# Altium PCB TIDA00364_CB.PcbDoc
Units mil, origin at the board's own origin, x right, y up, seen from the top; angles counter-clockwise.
Board outline 10290 x 3320 mil, 2 copper layers (Top Layer, Bottom Layer), stack 62 mil thick; 70 components, 9 nets, 112 pads, 0 vias.
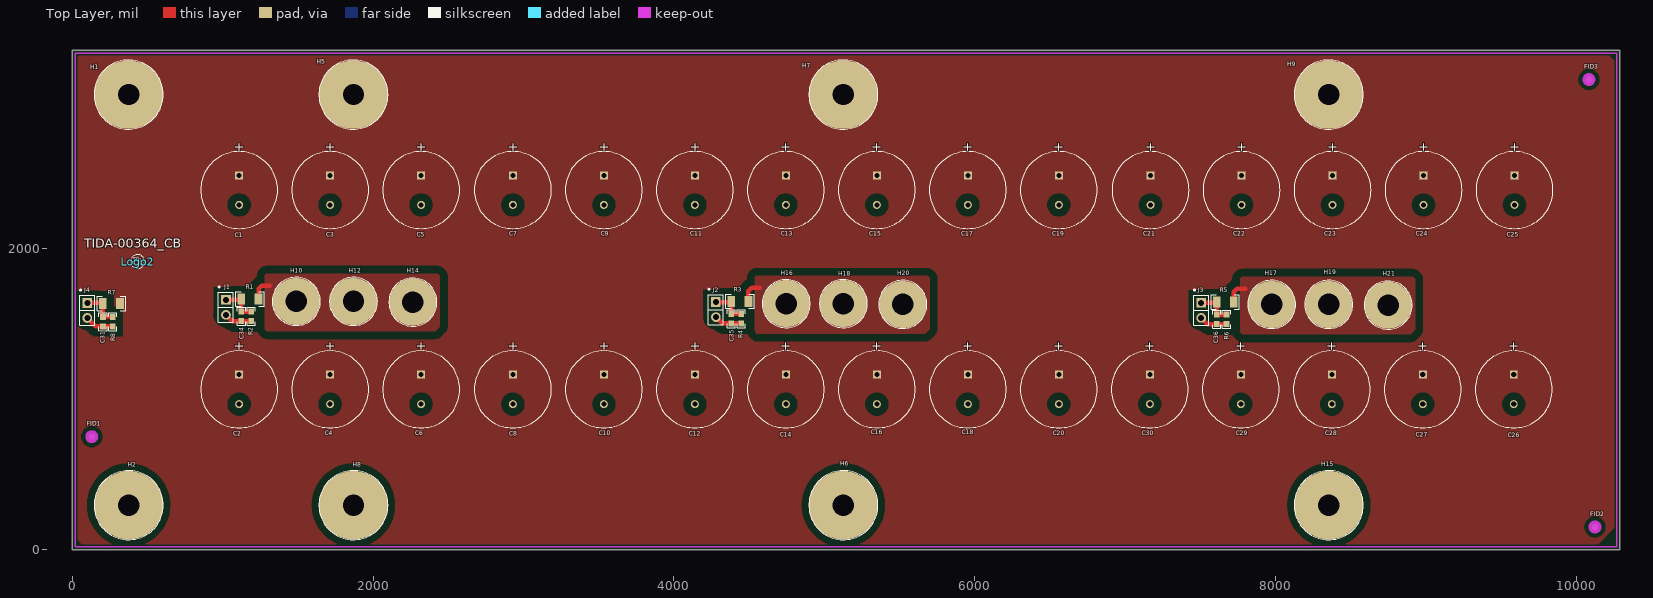
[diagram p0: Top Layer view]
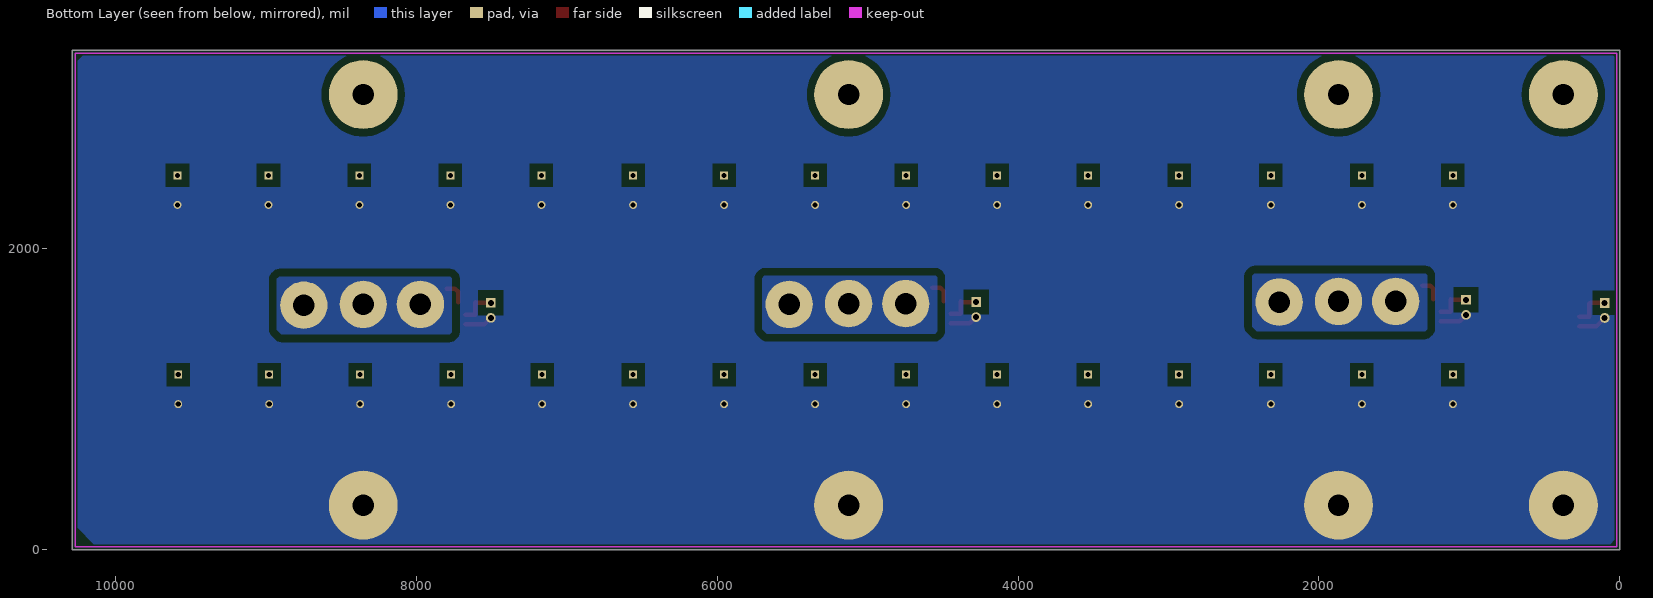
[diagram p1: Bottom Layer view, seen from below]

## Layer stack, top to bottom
Top Solder: solder mask 0.4, Solder Resist, Dk 3.5
Top Layer: signal copper 1.4
Dielectric1: core 59.2, FR-4, Dk 4.8
Bottom Layer: signal copper 1.4
Bottom Solder: solder mask 0.4, Solder Resist, Dk 3.5

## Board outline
0,0 0,3320 10290,3320 10290,0

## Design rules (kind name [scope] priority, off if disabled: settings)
AcuteAngle [All] p1: minimum=4.50000000000000E+0001 checktracksonly=FALSE
AssemblyTestPointUsage [All] p1: valid=2
Clearance Clearance_Boardedge_poly [OnCopper and InPolygon vs IsKeepOut] p1: gap=10
Clearance Clearance_PLANE [InPoly] p2: gap=50
Clearance "Clearance_via_thr pin" [IsVia vs IsThruPin] p3: gap=8
Clearance "Clearance_pad _class" [InPadClass('u12,u4,u5')] p4: gap=7.8
Clearance "SMD to Via" [IsSMTPin vs IsVia] p5: gap=8
Clearance [All] p6: gap=8
DiffPairsRouting DiffPair_DiffPairsRouting [InDifferentialPair ('kan')] p1: maxlimit=10 minlimit=10 mostfreqgap=10 toplayer_minwidth=15 toplayer_maxwidth=15 toplayer_prefwidth=15 bottomlayer_minwidth=15 bottomlayer_maxwidth=15 bottomlayer_prefwidth=15 maxuncoupledlength=500
DiffPairsRouting DiffPair_DiffPairsRouting_1 [InDifferentialPair ('kan')] p2: maxlimit=10 minlimit=10 mostfreqgap=10 toplayer_minwidth=15 toplayer_maxwidth=15 toplayer_prefwidth=15 bottomlayer_minwidth=15 bottomlayer_maxwidth=15 bottomlayer_prefwidth=15 maxuncoupledlength=500
DiffPairsRouting [All] p3: maxlimit=100 minlimit=10 mostfreqgap=10 toplayer_minwidth=15 toplayer_maxwidth=15 toplayer_prefwidth=15 bottomlayer_minwidth=15 bottomlayer_maxwidth=15 bottomlayer_prefwidth=15 maxuncoupledlength=1000
FabricationTestPointUsage TestPointUsage [All] p1: valid=2 allowmultiple=FALSE
FabricationTestpoint Testpoint [All] p1: side=3 testpointundercomponent=TRUE minsize=40 maxsize=100 preferedsize=60 minholesize=0 maxholesize=40 preferedholesize=32 testpointgrid=1 allowsidetop=TRUE allowsidebottom=TRUE usegrid=TRUE gridtolerance=0.01
FanoutControl Fanout_LCC [IsLCC] p1: bgadir=Out bgaviamode=Centered fanoutstyle=Auto fanoutdirection=Alternating viagrid=1 // Fanout_LCC (Default Rule)
FanoutControl Fanout_BGA [IsBGA] p2: bgadir=Out bgaviamode=Centered fanoutstyle=Auto fanoutdirection=Alternating viagrid=1 // Fanout_BGA (Default Rule)
FanoutControl Fanout_Default [All] p4: bgadir=Out bgaviamode=Centered fanoutstyle=Auto fanoutdirection=Alternating viagrid=1 // Fanout_Default (Default Rule)
FanoutControl Fanout_Small [(CompPinCount < 5)] p5: bgadir=Out bgaviamode=Centered fanoutstyle=Auto fanoutdirection=OutThenIn viagrid=1 // Fanout_Small (Default Rule)
HoleSize [All] p1: absolutevalues=TRUE maxlimit=500 minlimit=7 maxpercent=80.000 minpercent=20.000
MatchedLengths DiffPair_MatchedLengths [InDifferentialPair ('kan')] p1: tolerance=1000 checknetsindiffpair=TRUE checkdiffpairvsdiffpair=FALSE checkxsignals=FALSE checkothers=FALSE
MatchedLengths DiffPair_MatchedLengths_1 [InDifferentialPair ('kan')] p2: tolerance=1000 checknetsindiffpair=TRUE checkdiffpairvsdiffpair=FALSE checkxsignals=FALSE checkothers=FALSE
MinimumAnnularRing [All] p1: minimumring=5
MinimumAnnularRing MinimumAnnularRing_ThermalPadVias [IsVia and InAnyComponent] p2: minimumring=5.91
MinimumSolderMaskSliver MinimumSolderMaskSliver_Logo [InComponentClass('Logo') vs InComponentClass('Logo')] p1: minsoldermaskwidth=0.7
MinimumSolderMaskSliver [All] p2: minsoldermaskwidth=3.94
PlaneClearance [All] p1: clearance=15
PlaneConnect [All] p1: planeconnectstyle=Direct reliefexpansion=10 reliefentries=4 reliefconductorwidth=10 reliefairgap=10
PolygonConnect [All] p1: connectstyle=Direct reliefconductorwidth=10 reliefentries=4 polygonreliefangle="90 Angle" airgapwidth=10
RoutingVias RoutingVias_power [InNetClass('POWER')] p1: holewidth=16 width=32 viastyle="Through Hole" minholewidth=7.87 minwidth=19.68 maxholewidth=16 maxwidth=32
RoutingVias ThermalPadVias [IsVia and InAnyComponent] p2: holewidth=8 width=20 viastyle="Through Hole" minholewidth=7.87 minwidth=19 maxholewidth=12 maxwidth=24
RoutingVias [All] p3: holewidth=16 width=32 viastyle="Through Hole" minholewidth=12 minwidth=24 maxholewidth=20 maxwidth=40
SMDToCorner [All] p1: distance=30000
SilkToSilkClearance [All] p1: silktosilkclearance=5
SilkToSolderMaskClearance SilkscreenOverComponentPads [IsPad] p1: minsilkscreentomaskgap=5 clearancetoexposedcopper=TRUE
SolderMaskExpansion [All] p1: expansion=3
Width Width_power [InNetClass('POWER')] p1: maxlimit=100 minlimit=8 preferedwidth=20
Width [All] p2: maxlimit=100 minlimit=10 preferedwidth=10 checkconnectedcopper=TRUE
16 further rules are at their usual default settings.

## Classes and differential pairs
component class FiducialMark: FID1 FID2 FID3
component class AssemblyNote: ZZ1 ZZ2 ZZ3
component class TIDA00364_CB_CapacitorBank: C1 C2 C3 C4 C5 C6 C7 C8 C9 C10 C11 C12 C13 C14 C15 C16 C17 C18 C19 C20 C21 C22 C23 C24 C25 C26 C27 C28 C29 C30 C31 C34 C35 C36 J1 J2 J3 J4 R1 R2 R3 R4 R5 R6 R7 R8
component class TIDA00364_CB_Hardware: FID1 FID2 FID3 H1 H2 H5 H6 H7 H8 H9 H10 H12 H14 H15 H16 H17 H18 H19 H20 H21 Logo2 ZZ1 ZZ2 ZZ3
component class Header: J1 J2 J3 J4

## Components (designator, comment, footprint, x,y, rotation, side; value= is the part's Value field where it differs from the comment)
C1 "UHE2A121MHD6" HE_1250x2000 1110,2390 r270 top
C2 "UHE2A121MHD6" HE_1250x2000 1110,1065 r270 top
C3 "UHE2A121MHD6" HE_1250x2000 1715,2390 r270 top
C4 "UHE2A121MHD6" HE_1250x2000 1715,1065 r270 top
C5 "UHE2A121MHD6" HE_1250x2000 2320,2390 r270 top
C6 "UHE2A121MHD6" HE_1250x2000 2320,1065 r270 top
C7 "UHE2A121MHD6" HE_1250x2000 2930,2390 r270 top
C8 "UHE2A121MHD6" HE_1250x2000 2930,1065 r270 top
C9 "UHE2A121MHD6" HE_1250x2000 3535,2390 r270 top
C10 "UHE2A121MHD6" HE_1250x2000 3535,1065 r270 top
C11 "UHE2A121MHD6" HE_1250x2000 4140,2390 r270 top
C12 "UHE2A121MHD6" HE_1250x2000 4140,1065 r270 top
C13 "UHE2A121MHD6" HE_1250x2000 4745,2390 r270 top
C14 "UHE2A121MHD6" HE_1250x2000 4745,1065 r270 top
C15 "UHE2A121MHD6" HE_1250x2000 5350,2390 r270 top
C16 "UHE2A121MHD6" HE_1250x2000 5350,1065 r270 top
C17 "UHE2A121MHD6" HE_1250x2000 5955,2390 r270 top
C18 "UHE2A121MHD6" HE_1250x2000 5955,1065 r270 top
C19 "UHE2A121MHD6" HE_1250x2000 6560,2390 r270 top
C20 "UHE2A121MHD6" HE_1250x2000 6560,1065 r270 top
C21 "UHE2A121MHD6" HE_1250x2000 7170,2390 r270 top
C22 "UHE2A121MHD6" HE_1250x2000 7775,2390 r270 top
C23 "UHE2A121MHD6" HE_1250x2000 8380,2390 r270 top
C24 "UHE2A121MHD6" HE_1250x2000 8985,2390 r270 top
C25 "UHE2A121MHD6" HE_1250x2000 9590,2390 r270 top
C26 "UHE2A121MHD6" HE_1250x2000 9585,1065 r270 top
C27 "UHE2A121MHD6" HE_1250x2000 8980,1065 r270 top
C28 "UHE2A121MHD6" HE_1250x2000 8375,1065 r270 top
C29 "UHE2A121MHD6" HE_1250x2000 7770,1065 r270 top
C30 "UHE2A121MHD6" HE_1250x2000 7165,1065 r270 top
C31 "C1608X7R1H103K" 0603 205,1515 r270 top
C34 "C1608X7R1H103K" 0603 1125,1550 r270 top
C35 "C1608X7R1H103K" 0603 4382.64,1535 r270 top
C36 "C1608X7R1H103K" 0603 7610,1530 r270 top
FID1 "Fiducial" Fiducial10-20 130,750 r90 top
FID2 "Fiducial" Fiducial10-20 10125,150 r90 top
FID3 "Fiducial" Fiducial10-20 10085,3125 r90 top
H1 "RM3X8MM 2701" "APM_RM3X8MM 2701"#1 375,3025.01 r0 top
H2 "RM3X8MM 2701" "APM_RM3X8MM 2701"#1 375,295.01 r0 top
H5 "RM3X8MM 2701" "APM_RM3X8MM 2701"#1 1870,3025.01 r0 top
H6 "RM3X8MM 2701" "APM_RM3X8MM 2701"#1 5127.64,295.01 r0 top
H7 "RM3X8MM 2701" "APM_RM3X8MM 2701"#1 5127.64,3025.01 r0 top
H8 "RM3X8MM 2701" "APM_RM3X8MM 2701"#1 1870,295.01 r0 top
H9 "RM3X8MM 2701" "APM_RM3X8MM 2701"#1 8355,3025.01 r0 top
H10 "RM3X8MM 2701" "APM_RM3X8MM 2701"#2 1490,1650.01 r0 top
H12 "RM3X8MM 2701" "APM_RM3X8MM 2701"#2 1870,1650.01 r0 top
H14 "RM3X8MM 2701" "APM_RM3X8MM 2701"#2 2265,1645.01 r0 top
H15 "RM3X8MM 2701" "APM_RM3X8MM 2701"#1 8355,295.01 r0 top
H16 "RM3X8MM 2701" "APM_RM3X8MM 2701"#2 4747.64,1635.01 r0 top
H17 "RM3X8MM 2701" "APM_RM3X8MM 2701"#2 7975,1630.01 r0 top
H18 "RM3X8MM 2701" "APM_RM3X8MM 2701"#2 5127.64,1635.01 r0 top
H19 "RM3X8MM 2701" "APM_RM3X8MM 2701"#2 8355,1630.01 r0 top
H20 "RM3X8MM 2701" "APM_RM3X8MM 2701"#2 5522.64,1630.01 r0 top
H21 "RM3X8MM 2701" "APM_RM3X8MM 2701"#2 8750,1625.01 r0 top
J1 "90120-0122" CONN_90120-0122 1021.93,1610.43 r270 top
J2 "90120-0122" CONN_90120-0122 4279.57,1595.43 r270 top
J3 "90120-0122" CONN_90120-0122 7506.93,1590.43 r270 top
J4 "90120-0122" CONN_90120-0122 100,1590 r270 top
Logo2 "Pb-Free Symbol" Pb-Free_Overlay_Small 435,1915 r0 top
R1 "CRCW1206200KFKEA" 1206 1181.93,1665.43 r180 top
R2 "CRCW060310K0FKEA" 0603 1190,1550 r90 top
R3 "CRCW1206200KFKEA" 1206 4439.57,1650.43 r180 top
R4 "CRCW060310K0FKEA" 0603 4447.64,1535 r90 top
R5 "CRCW1206200KFKEA" 1206 7666.93,1645.43 r180 top
R6 "CRCW060310K0FKEA" 0603 7675,1530 r90 top
R7 "CRCW1206200KFKEA" 1206 260,1635 r180 top
R8 "CRCW060310K0FKEA" 0603 270,1515 r90 top
ZZ1 "These assemblies are ESD sensitive, ESD precautions shall be observed." AssemblyNote 757.92,4115.63 r0 top
ZZ2 "These assemblies must be clean and free from flux and all contaminants. Use of no clean flux is not acceptable." AssemblyNote 757.92,4040.63 r0 top
ZZ3 "These assemblies must comply with workmanship standards IPC-A-610 Class 2, unless otherwise specified." AssemblyNote 755,3945 r0 top

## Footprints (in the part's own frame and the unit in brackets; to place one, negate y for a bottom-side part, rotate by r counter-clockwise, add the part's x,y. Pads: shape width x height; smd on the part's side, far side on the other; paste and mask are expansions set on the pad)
0603 [mm] "0603 from SM-752 data"
  rect 1x0.95 smd: 1(-0.8,0) 2(0.8,0)
  silkscreen extent -1.52,-0.69 1.52,0.69, body extent -0.87,-0.47 0.87,0.47, height 1
1206 [mm] "1206 from SM-752 data"
  rect 1.3x1.85 smd: 1(-1.45,0) 2(1.45,0)
  silkscreen extent -2.4,-1.21 2.4,1.21, body extent -1.7,-0.9 1.7,0.9, height 1.35
"APM_RM3X8MM 2701"#1 [mil] "Screw, Dia 6.7mm, Length 8mm, TH"
  round 458 hole 141.73: ""(0,0)
  silkscreen extent -230,-230 230,230, body extent -131,-132 132,132, height 94
"APM_RM3X8MM 2701"#2 [mil] "Screw, Dia 6.7mm, Length 8mm, TH"
  round 314.96 hole 141.73: ""(0,0)
  silkscreen extent -160,-160 160,160, body extent -131,-132 132,132, height 94
AssemblyNote [mil] "Assembly Note"
CONN_90120-0122 [mm] "Molex"
  rect 1.65x1.65 hole 1.016 mask+0: 1(-1.27,0)
  round 1.65 hole 1.016 mask+0: 2(1.27,0)
  silkscreen extent -3.56,-1.27 2.54,1.27, body extent -2.54,-1.27 2.54,1.27, height 9.29
Fiducial10-20 [mm]
  round 1 smd mask+0.5: 1(0,0)
  Top Layer keep-out circle w1.178: c0,0 r0.5
HE_1250x2000 [mm] "TH, 2-Leads, Dia 12.5, Pin Spacing 5mm"
  rect 1.35x1.35 hole 0.85: 1(-2.5,0)
  round 1.35 hole 0.85: 2(2.5,0)
  silkscreen extent -6.5,-6.5 6.5,6.5, body extent -6.45,-6.49 6.51,6.49, height 22
Pb-Free_Overlay_Small [mil]
  silkscreen extent -46,-46 46,46

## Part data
C1 C2 C3 C4 C5 C6 C7 C8 C9 C10 C11 C12 C13 C14 C15 C16 C17 C18 C19 C20 C21 C22 C23 C24 C25 C26 C27 C28 C29 C30: "CAP, AL, 120 µF, 100 V, +/- 20%, 0.16 ohm, TH"
C31 C34 C35 C36: "CAP, CERM, 0.01 µF, 50 V, +/- 10%, X7R, 0603"
FID1 FID2 FID3: "Fiducial mark.  There is nothing to buy or mount."
H1 H2 H5 H6 H7 H8 H9 H10 H12 H14 H15 H16 H17 H18 H19 H20 H21: "MACHINE SCREW PAN PHILLIPS M3"
J1 J2 J3 J4: "Header, 100mil, 2x1, Tin, TH"
Logo2: library part Pb-Free
R1 R3 R5 R7: "RES, 200 k, 1%, 0.25 W, 1206"
R2 R4 R6 R8: "RES, 10.0 k, 1%, 0.1 W, 0603"
ZZ1 ZZ2 ZZ3: library part AssemblyNote

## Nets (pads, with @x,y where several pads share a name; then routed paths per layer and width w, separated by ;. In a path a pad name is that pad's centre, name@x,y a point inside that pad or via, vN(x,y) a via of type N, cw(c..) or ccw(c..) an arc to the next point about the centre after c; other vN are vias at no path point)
48V: C1.1 C2.1 C3.1 C4.1 C5.1 C6.1 C7.1 C8.1 C9.1 C10.1 C11.1 C12.1 C13.1 C14.1 C15.1 C16.1 C17.1 C18.1 C19.1 C20.1 C21.1 C22.1 C23.1 C24.1 C25.1 C26.1 C27.1 C28.1 C29.1 C30.1 H1. H5. H7. H9. R7.1
48V_RTN: C1.2 C2.2 C3.2 C4.2 C5.2 C6.2 C7.2 C8.2 C9.2 C10.2 C11.2 C12.2 C13.2 C14.2 C15.2 C16.2 C17.2 C18.2 C19.2 C20.2 C21.2 C22.2 C23.2 C24.2 C25.2 C26.2 C27.2 C28.2 C29.2 C30.2 C31.2 C34.2 C35.2 C36.2 H2. H6. H8. H15. J1.2 J2.2 J3.2 J4.2 R2.1 R4.1 R6.1 R8.1 | length 749.7
  Top Layer w30: J4.2 156.5,1483.5 C31.2 R8.1 ; J1.2 1063.86,1518.5 C34.2 R2.1 ; J2.2 4321.5,1503.5 C35.2 R4.1 ; J3.2 7548.86,1498.5 C36.2 R6.1
PHASE_U: H10. H12. H14. R1.1 | length 153.3
  Top Layer w30: R1.1 1239.02,1734.02 1260,1755 1315,1755
PHASE_V: H16. H18. H20. R3.1 | length 153.3
  Top Layer w30: R3.1 4496.65,1719.02 4517.64,1740 4572.64,1740
PHASE_W: H17. H19. H21. R5.1 | length 153.3
  Top Layer w30: R5.1 7724.02,1714.02 7745,1735 7800,1735
PHV_U_FB: C34.1 J1.1 R1.2 R2.2 | length 254
  Top Layer w30: J1.1 1119.84,1660.43 R1.2 1124.84,1581.65 C34.1 R2.2
PHV_V_FB: C35.1 J2.1 R3.2 R4.2 | length 254
  Top Layer w30: J2.1 4377.48,1645.43 R3.2 4382.48,1566.65 C35.1 R4.2
PHV_W_FB: C36.1 J3.1 R5.2 R6.2 | length 254
  Top Layer w30: J3.1 7604.84,1640.43 R5.2 7609.84,1561.65 C36.1 R6.2
VDC_FB: C31.1 J4.1 R7.2 R8.2 | length 259.4
  Top Layer w30: J4.1 197.91,1640 R7.2 202.91,1548.58 C31.1 R8.2
pads on no net: FID1.1 FID2.1 FID3.1

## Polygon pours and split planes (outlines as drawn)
48V on Top Layer "Top Layer-No Net" (solid, remove dead copper, pour order 16): 60,3300 10205,3300 10270,3235 10270,160 10135,25 75,25 20,80 20,3260
PHASE_U on Top Layer "Top Layer-No Net" (solid, remove dead copper, pour order 9): 1305,1835 2430,1835 2445,1820 2445,1480 2415,1450 1295,1450 1280,1465 1280,1825 1290,1835
PHASE_V on Top Layer "Top Layer-No Net" (solid, remove dead copper, pour order 10): 4562.64,1820 5687.64,1820 5702.64,1805 5702.64,1465 5672.64,1435 4552.64,1435 4537.64,1450 4537.64,1810 4547.64,1820
PHASE_W on Top Layer "Top Layer-No Net" (solid, remove dead copper, pour order 11): 7790,1815 8915,1815 8930,1800 8930,1460 8900,1430 7780,1430 7765,1445 7765,1805 7775,1815
48V_RTN on Bottom Layer "Top Layer-No Net" (solid, remove dead copper, pour order 15): 60,3300 10205,3300 10270,3235 10270,160 10135,25 75,25 20,80 20,3260
PHASE_U on Bottom Layer "Top Layer-No Net" (solid, remove dead copper, pour order 14): 1305,1835 2430,1835 2445,1820 2445,1480 2415,1450 1295,1450 1280,1465 1280,1825 1290,1835
PHASE_V on Bottom Layer "Top Layer-No Net" (solid, remove dead copper, pour order 12): 4562.64,1820 5687.64,1820 5702.64,1805 5702.64,1465 5672.64,1435 4552.64,1435 4537.64,1450 4537.64,1810 4547.64,1820
PHASE_W on Bottom Layer "Top Layer-No Net" (solid, remove dead copper, pour order 13): 7790,1815 8915,1815 8930,1800 8930,1460 8900,1430 7780,1430 7765,1445 7765,1805 7775,1815

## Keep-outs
Keep-Out Layer:
  lines w10: 20,20 10270,20 10270,3300 20,3300 20,20
  text ".Layer_Name" at 354.92,-1532.86 h60

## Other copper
Top Layer:
  text ".layer_Name" at 369.92,-1522.37 h60
Bottom Layer:
  text ".Layer_Name" at 428.92,-1532.37 h60

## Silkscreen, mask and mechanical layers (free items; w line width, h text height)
Top Overlay:
  text "TIDA-00364_CB" at 80,2005 h60
  text ".layer_Name" at 395.92,-1520.37 h60
Bottom Overlay:
  text ".Layer_Name" at 354.92,-1532.86 h60
Top Paste:
  text ".Layer_Name" at 342.92,-1535.86 h60
Bottom Paste:
  text ".Layer_Name" at 342.92,-1535.86 h60
Top Solder:
  text ".Layer_Name" at 370.92,-1543.37 h60
Bottom Solder:
  text ".Layer_Name" at 417.92,-1539.37 h60
M1 Board Outline:
  the board outline again, w10
  text "'.Layer_Name'" at 730,-1530 h72.83
M2 Board Dimensions:
  rectangle: -260.58,-1019.37 114.42,-894.37
  rectangle: -385.58,-894.37 -260.58,-769.37
  lines w7: -385.58,-894.37 614.42,-894.37 ; -260.58,-1019.37 -260.58,-769.37 ; -135.58,-1019.37 -135.58,-769.37 ; 114.42,-1019.37 114.42,-769.37 ; 364.42,-1019.37 364.42,-769.37 ; -385.58,-1019.37 -385.58,-769.37 614.42,-769.37 614.42,-1019.37 -385.58,-1019.37
M3 3D STEP Top:
  text ".Layer_Name" at 354.92,-1532.86 h60
M4 3D STEP Bottom:
  text ".Layer_Name" at 354.92,-1532.86 h60
M5 Assembly Top:
  lines w10: -514.08,-1604.53 6085.92,-1604.53 ; -514.08,-1401.2 6087.92,-1401.2 ; -514.08,-1197.87 -514.08,-1807.87 3490.92,-1807.87 6087.92,-1807.87 6087.92,-1197.87 -513.58,-1197.87 -513.58,-1807.87 ; 1950.92,-1807.87 1950.92,-1197.87 ; 3217.92,-1401.2 3217.92,-1197.87 ; 4057.92,-1401.2 4057.92,-1197.87 ; 4679.92,-1814.37 4679.92,-1611.53
  text "COMPONENTS MARKED 'DNP' SHOULD NOT BE POPULATED." at 931.42,-992.87 h30
  text "ASSEMBLY VARIANT:" at 930.92,-1108.37 h30
  text ".VariantName" at 1966.92,-1108.37 h30
  text "ALL ARTWORK VIEWED FROM TOP SIDE" at -450.58,-1330.03 h30
  text "BOARD #:" at 2025.92,-1330.03 h30
  text ".PRJ_Number" at 2571.42,-1330.03 h30
  text "REV:" at 3415.92,-1330.03 h30
  text ".PCB_Rev" at 3707.42,-1330.03 h30
  text "SVN REV:" at 4253.92,-1330.03 h30
  text ".VersionControl_RevNumber" at 4759.92,-1330.03 h30
  text ".layer_Name" at 312.92,-1512.37 h30
  text "LAYER NAME =" at -457.08,-1519.37 h30
  text ".plot_File_Name" at -459.08,-1708.37 h30
  text "GENERATED    :" at 2027.92,-1738.7 h30
  text ".Print_Date" at 2897.42,-1738.7 h30
  text ".Print_Time" at 3626.42,-1738.7 h30
  text "TEXAS INSTRUMENTS" at 4890.92,-1738.7 h30
M6 Assembly Bottom:
  lines w10: -514.58,-1401.7 6087.42,-1401.7 ; -512.58,-1605.03 6087.42,-1605.03 ; 1515.42,-1401.7 1515.42,-1198.37 ; 2355.42,-1401.7 2355.42,-1198.37 ; 3622.42,-1808.37 3622.42,-1198.37 ; 4511.42,-1808.37 6086.92,-1808.37 6086.92,-1198.37 -514.58,-1198.37 -514.58,-1808.37 2082.42,-1808.37 6087.42,-1808.37 6087.42,-1198.37
  text "COMPONENTS MARKED 'DNP' SHOULD NOT BE POPULATED." at 5879.92,-992.37 h30
  text ".VariantName" at 4835.92,-1108.37 h30
  text "ASSEMBLY VARIANT:" at 5874.92,-1108.37 h30
  text "SVN REV:" at 1319.42,-1330.53 h30
  text ".PCB_Rev" at 1865.92,-1330.53 h30
  text "REV:" at 2157.42,-1330.53 h30
  text ".PRJ_Number" at 3001.92,-1330.53 h30
  text "BOARD #:" at 3547.42,-1330.53 h30
  text "PCB VIEWED FROM BOTTOM SIDE" at 6023.92,-1330.53 h30
  text "LAYER NAME =" at 6018.92,-1515.37 h30
  text ".Layer_Name" at 5245.92,-1522.37 h30
  text "IGNORE ->" at 2325.77,-1532.86 h30
  text ".Print_Time" at 1946.92,-1739.2 h30
  text ".Print_Date" at 2675.92,-1739.2 h30
  text "GENERATED    :" at 3545.42,-1739.2 h30
  text ".plot_File_Name" at 5218.42,-1739.2 h30
  text "PLOT NAME =" at 6023.92,-1739.2 h30
M9 Title Sheet:
  drawing of 56 lines, arcs and shapes, not listed
  text "1" at 517.76,7362.13 h70
  text "2" at 3013.42,7362.13 h70
  text "3" at 5502.76,7362.13 h70
  text "4" at 8009.43,7362.13 h70
  text "5" at 10508.42,7362.13 h70
  text "6" at 13013.42,7362.13 h70
  text "A" at 19196.42,6389.13 h70
  text "A" at -638.58,6219.13 h70
  text "B" at 19196.42,4009.13 h70
  text "B" at -638.58,3839.13 h70
  text "C" at 19196.42,1634.13 h70
  text "C" at -638.58,1464.13 h70
  text "PROJECT TITLE:" at 16156.42,-226.87 h45
  text ".PRJ_Title" at 16576.92,-363.37 h70
  text "DESIGNED FOR:" at 16156.42,-527.87 h45
  text ".PRJ_Customer" at 16206.42,-667.87 h70
  text "D" at 19196.42,-735.87 h70
  text "FILE NAME:" at 16156.42,-827.87 h45
  text "D" at -638.58,-905.87 h70
  text ".PCB_File_Name_No_Path" at 16206.42,-947.87 h70
  text "ENGINEER:" at 16156.42,-1117.87 h45
  text "LAYOUT BY:" at 17661.42,-1117.87 h45
  text ".PRJ_Engineer" at 16206.42,-1272.86 h70
  text ".PCB_Layout" at 17711.92,-1272.86 h70
  text "Texas Instruments (TI) and/or its licensors do not warrant the accuracy or completeness of this specification" at 6151.92,-1279.71 h45
  text "or any information contained therein. TI and/or its licensors do not warrant that this design will meet" at 6106.93,-1392.37 h45
  text "ALTIUM DESIGNER VERSION:" at 17661.42,-1427.87 h45
  text "the specifications, will be suitable for your application or fit for any particular purpose, or will operate in" at 6106.93,-1505.04 h45
  text ".print_Scale" at 16206.42,-1561.19 h70
  text ".Application_BuildNumber" at 17711.92,-1561.19 h70
  text "an implementation. TI and/or its licensors do not warrant that the design is production worthy. You should" at 6106.93,-1617.7 h45
  text "completely validate and test your design implementation to confirm the system functionality for your application." at 6151.92,-1730.37 h45
  text "6" at 18048.42,-1767.87 h70
  text "2" at 3013.42,-1937.87 h70
  text "3" at 5502.76,-1937.87 h70
  text "4" at 8009.43,-1937.87 h70
  text "5" at 10508.42,-1937.87 h70
M10 Fab Notes:
  drawing of 228 lines, arcs and shapes, not listed
  text "DESIGN INFORMATION" at 17193.94,6305.63 h60
  text "(REFER ALSO ARRAY/PANEL PROFILING INFORMATION)" at 16832.38,6143.92 h60
  text "BOARD SIZE" at 16146.38,6139.63 h60
  text "84.33MM" at 17285,6020 h60
  text "X" at 17114.38,6011.81 h60
  text "261.37MM" at 16550,6010 h60
  text "Number of Layers :" at 16549.38,5814.63 h60
  text "2" at 17644.19,5804.64 h60
  text "30" at 17590,5685 h60
  text "MIN. TRACK WIDTH:" at 16549.38,5675.63 h60
  text "MIL" at 17800.38,5675.63 h60
  text "20" at 17580,5555 h60
  text "MIN. CLEARANCE:" at 16549.38,5543.63 h60
  text "MIL" at 17800.38,5543.63 h60
  text "MIN. VIA DRILL SIZE:" at 16549.38,5411.63 h60
  text "MIL" at 17800.38,5411.63 h60
  text "33.465" at 17425,5410 h60
  text "7.345MIL" at 17244.38,5269.92 h60
  text "MINIMUM ANNULAR RING" at 16220.15,5265.64 h60
  text "EXTERNAL" at 17952.38,5265.64 h60
  text "PER" at 16420.15,5147.64 h60
  text "IPC-D-275 CLASS 2 LEVEL C" at 16640.15,5147.63 h60
  text "MIL, HOLES" at 18128.38,5035.35 h60
  text "+/-" at 17735.92,5034.64 h60
  text "+/-" at 18589.92,5034.64 h60
  text "REGISTRATION TOLERANCES:" at 16220.15,5029.63 h60
  text "METAL" at 17419.92,5029.63 h60
  text "5" at 17996.12,5029.64 h60
  text "3" at 18829.12,5029.64 h60
  text "MIL" at 18945.38,5029.63 h60
  text "MATERIAL:" at 16145.38,4820.18 h60
  text "FR-4 High Tg" at 17131.82,4679.84 h60
  text "X" at 16940,4675 h60
  text "FR-408" at 16566.38,4671.27 h60
  text "OTHER" at 18054.38,4671.27 h60
  text "X" at 16715,4510 h60
  text "63 MIL (1.6mm) +/-10%" at 16886.48,4508.56 h60
  text "THICKNESS:" at 16220.15,4504.27 h60
  text "OTHER" at 18171.38,4504.27 h60
  text "X" at 17025,4350 h60
  text "TOLERANCE:" at 16220.15,4346.27 h60
  text "ANSI IPC-6012 TYPE 3 CLASS 2" at 17246.39,4346.27 h60
  text "OTHER +/-" at 17246.38,4190.27 h60
  text "X" at 17030,4040 h60
  text "BOW & TWIST:" at 16220.15,4033.27 h60
  text "ANSI IPC-6012 TYPE 3 CLASS 2" at 17246.39,4033.27 h60
  text "OTHER +/-" at 17246.38,3874.77 h60
  text "COPPER THICKNESS (FINISHED):" at 16145.38,3739.27 h60
  text "X" at 18365,3600 h60
  text "1.4MIL (1oz)" at 17025.38,3586.56 h60
  text "2MIL (1.4oz)" at 17792.38,3586.56 h60
  text "2.8MIL (2oz)" at 18519.38,3586.56 h60
  text "OUTER:" at 16502.38,3582.27 h60
  text "1.4MIL (1oz)" at 17025.38,3429.56 h60
  text "2.8MIL (2oz)" at 17792.38,3429.56 h60
  text "N/A" at 18518.92,3429.92 h60
  text "INNER SIGNAL:" at 16213.3,3425.27 h60
  text "DRILLING:" at 16145.38,3286.27 h60
  text "X" at 16840,3185 h60
  text "X" at 17735,3180 h60
  text "REFERENCE:" at 16220.15,3169.27 h60
  text "AS SHOWN" at 17055.38,3169.27 h60
  text "NC_DRILL FILES" at 17906.38,3169.27 h60
  text "X" at 17525,3020 h60
  text "PTH MIN COPPER THICKNESS:" at 16220.15,3011.27 h60
  text "1MIL" at 17707.38,3011.27 h60
  text "OTHER" at 18204.38,3011.27 h60
  text "BOARD FINISH:" at 16145.38,2852.27 h60
  text "X" at 17210,2740 h60
  text "SILKSCREEN:" at 16300.6,2734.27 h60
  text "TOP" at 17375.38,2734.27 h60
  text "BOTTOM" at 17886.38,2734.27 h60
  text "X" at 17210,2575 h60
  text "SILKSCREEN COLOR:" at 16300.6,2567.27 h60
  text "WHITE" at 17375.38,2567.27 h60
  text "OTHER" at 17886.38,2567.27 h60
  text "SOLDER RESIST COLOR:" at 16300.6,2397.27 h60
  text "X" at 16830,2245 h60
  text "GREEN" at 16995.38,2238.08 h60
  text "BLUE" at 17586.38,2238.08 h60
  text "OTHER" at 18124.38,2238.08 h60
  text "X" at 16980,2055 h60
  text "IMMERSION GOLD (ENIG)" at 17206.38,2049.56 h60
  text "ENEPIG" at 18543.92,2046.27 h60
  text "SURFACE FINISH:" at 16145.38,2045.27 h60
  text "IMM. TIN/SILVER OR EQUIV" at 16474.92,1888.27 h60
  text "OTHER" at 17906.38,1888.27 h60
  text "ARRAY/PANEL:" at 16145.38,1709.27 h60
  text "CUT AND TRIM PER MECH LAYER 1" at 17206.38,1704.99 h60
  text "X" at 17850,1560 h60
  text "N.C. ROUTE" at 17206.38,1553.27 h60
  text "V. SCORE" at 18072.38,1553.27 h60
  text "CERTIFICATION:" at 16145.38,1416.27 h60
  text "MATERIALS AND WORKMANSHIP FOR ALL PCBS" at 16870.38,1416.27 h60
  text "TO MEET OR EXCEED THE REQUIREMENTS OF:" at 16870.38,1318.27 h60
  text "X" at 16460,1190 h60
  text "X" at 18245,1185 h60
  text "ANSI IPC-A-600F CLASS ->" at 16605.88,1181.77 h60
  text "2" at 18393.88,1181.77 h60
  text "1" at 18078.88,1180.27 h60
  text "3" at 18747.88,1180.27 h60
  text "X" at 17275,1040 h60
  text "UL 94V-0" at 16635.88,1022.27 h60
  text "RoHS" at 17447.88,1022.27 h60
  text "OTHER" at 18092.28,1022.27 h60
  text "PER ORDER" at 18489.34,1022.27 h60
  text "X" at 16470,1020 h60
  text "VIA TENTING:" at 17362.92,888.63 h60
  text "ADDITIONAL REQUIREMENTS:" at 16145.38,881.27 h60
  text "YES" at 17885,880 h60
  text "NO" at 18235,880 h60
  text "MICROSECTION:" at 16220.15,766.27 h60
  text "YES" at 17125.88,766.27 h60
  text "IMPEDANCE CONTROL:" at 17384.92,759.63 h60
  text "YES" at 18340,760 h60
  text "X" at 18880,755 h60
  text "NO" at 18700,750 h60
  text "X" at 17835,610 h60
  text "REQUIRED" at 17970,610 h60
  text "BARE BOARD ELEC. TEST:" at 16220.15,607.27 h60
  text "NONE" at 17525.88,607.27 h60
  text "PER ORDER" at 18579.38,607.27 h60
  text "X" at 18205,455 h60
  text "MANUFACTURER'S UL:" at 16220.15,450.27 h60
  text "RAIL" at 17385.88,445.99 h60
  text "METAL" at 17877.69,445.99 h60
  text "SILK" at 18389.38,445.99 h60
M11 Gerber Information:
  lines w10: -514.08,-1604.53 6085.92,-1604.53 ; -514.08,-1401.2 6087.92,-1401.2 ; -514.08,-1197.87 -514.08,-1807.87 3490.92,-1807.87 6087.92,-1807.87 6087.92,-1197.87 -513.58,-1197.87 -513.58,-1807.87 ; 1950.92,-1807.87 1950.92,-1197.87 ; 3217.92,-1401.2 3217.92,-1197.87 ; 4057.92,-1401.2 4057.92,-1197.87 ; 4679.92,-1814.37 4679.92,-1611.53
  text "BOARD #:" at 2025.92,-1330.03 h60
  text ".PRJ_Number" at 2571.42,-1330.03 h40
  text "REV:" at 3415.92,-1330.03 h60
  text ".PCB_Rev" at 3707.42,-1330.03 h60
  text "SVN REV:" at 4253.92,-1330.03 h60
  text ".VersionControl_RevNumber" at 4759.92,-1330.03 h60
  text "ALL ARTWORK VIEWED FROM TOP SIDE" at -451.58,-1336.03 h60
  text "LAYER NAME =" at -453.08,-1519.37 h60
  text ".plot_File_Name" at -461.08,-1718.37 h60
  text "GENERATED    :" at 2027.92,-1738.7 h60
  text ".Print_Date" at 2897.42,-1738.7 h60
  text ".Print_Time" at 3626.42,-1738.7 h60
  text "TEXAS INSTRUMENTS" at 4890.92,-1738.7 h60
M12 Stackup:
  lines w6: 16132.92,6960.63 18682.92,6960.63 ; 16132.92,7065.03 18682.92,7065.03 ; 16072.92,6475.63 ccw(c16106.92,6475.63) 16106.92,6441.63 18708.92,6441.63 ccw(c18708.92,6475.63) 18742.92,6475.63 18742.92,7181.63 ccw(c18708.92,7181.63) 18708.92,7215.63 16106.92,7215.63 ccw(c16106.92,7181.63) 16072.92,7181.63 16072.92,6475.63
  text "Layer Stack Up Detail for: TIDA-00364_CB_E1" at 16172.92,7092.73 h57
  text "Layer" at 16172.92,7021.03 h24
  text "Gerber" at 17068.73,7021.03 h24
  text "Copper" at 17632.25,7021.03 h24
  text "Dielectric" at 18234.96,7021.03 h24
  text "Name" at 16172.92,6973.03 h24
  text "Document" at 17068.73,6973.03 h24
  text "Thickness" at 17632.25,6973.03 h24
  text "Material" at 18234.96,6973.03 h24
  text "Top Solder Mask" at 16172.92,6880.07 h34
  text "(.GTS)" at 17068.73,6880.07 h34
  text "Solder Resist" at 18234.96,6880.07 h34
  text "Top Layer" at 16172.92,6783.32 h34
  text "(.GTL)" at 17068.73,6783.32 h34
  text "2.8mil" at 17632.25,6783.32 h34
  text "FR-4 Hg Tg" at 18263.92,6782.63 h34
  text "FR-4 Hg Tg" at 18265.92,6693.63 h34
  text "Bottom Layer" at 16178.92,6683.63 h34
  text "(.GBL)" at 17076.92,6682.63 h34
  text "2.8mil" at 17636.92,6676.63 h34
  text "Solder Resist" at 18228.92,6609.63 h34
  text "(.GBS)" at 17073.92,6602.63 h34
  text "Bottom Solder Mask" at 16175.92,6597.63 h34
M13 Component Bodies Top:
  text ".Layer_Name" at 354.92,-1532.86 h60
M14 Component Bodies Bottom:
  text ".Layer_Name" at 354.92,-1532.86 h60
M15 Courtyards Top:
  text ".Layer_Name" at 354.92,-1532.86 h60
M16 Courtyards Bottom:
  text ".Layer_Name" at 354.92,-1532.86 h60
Drill Drawing:
  text "Drill Table" at 6544.92,4974.63 h60
  text "FOR PTH DRILL +/-3MIL" at 6551.92,4842.63 h60
  text ".legend" at 6545,4740 h60
  text ".layer_Name" at 459.92,-1516.37 h60

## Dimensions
0,0 to 0,3320 on M2 Board Dimensions
0,3320 to 10290,3320 on M2 Board Dimensions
